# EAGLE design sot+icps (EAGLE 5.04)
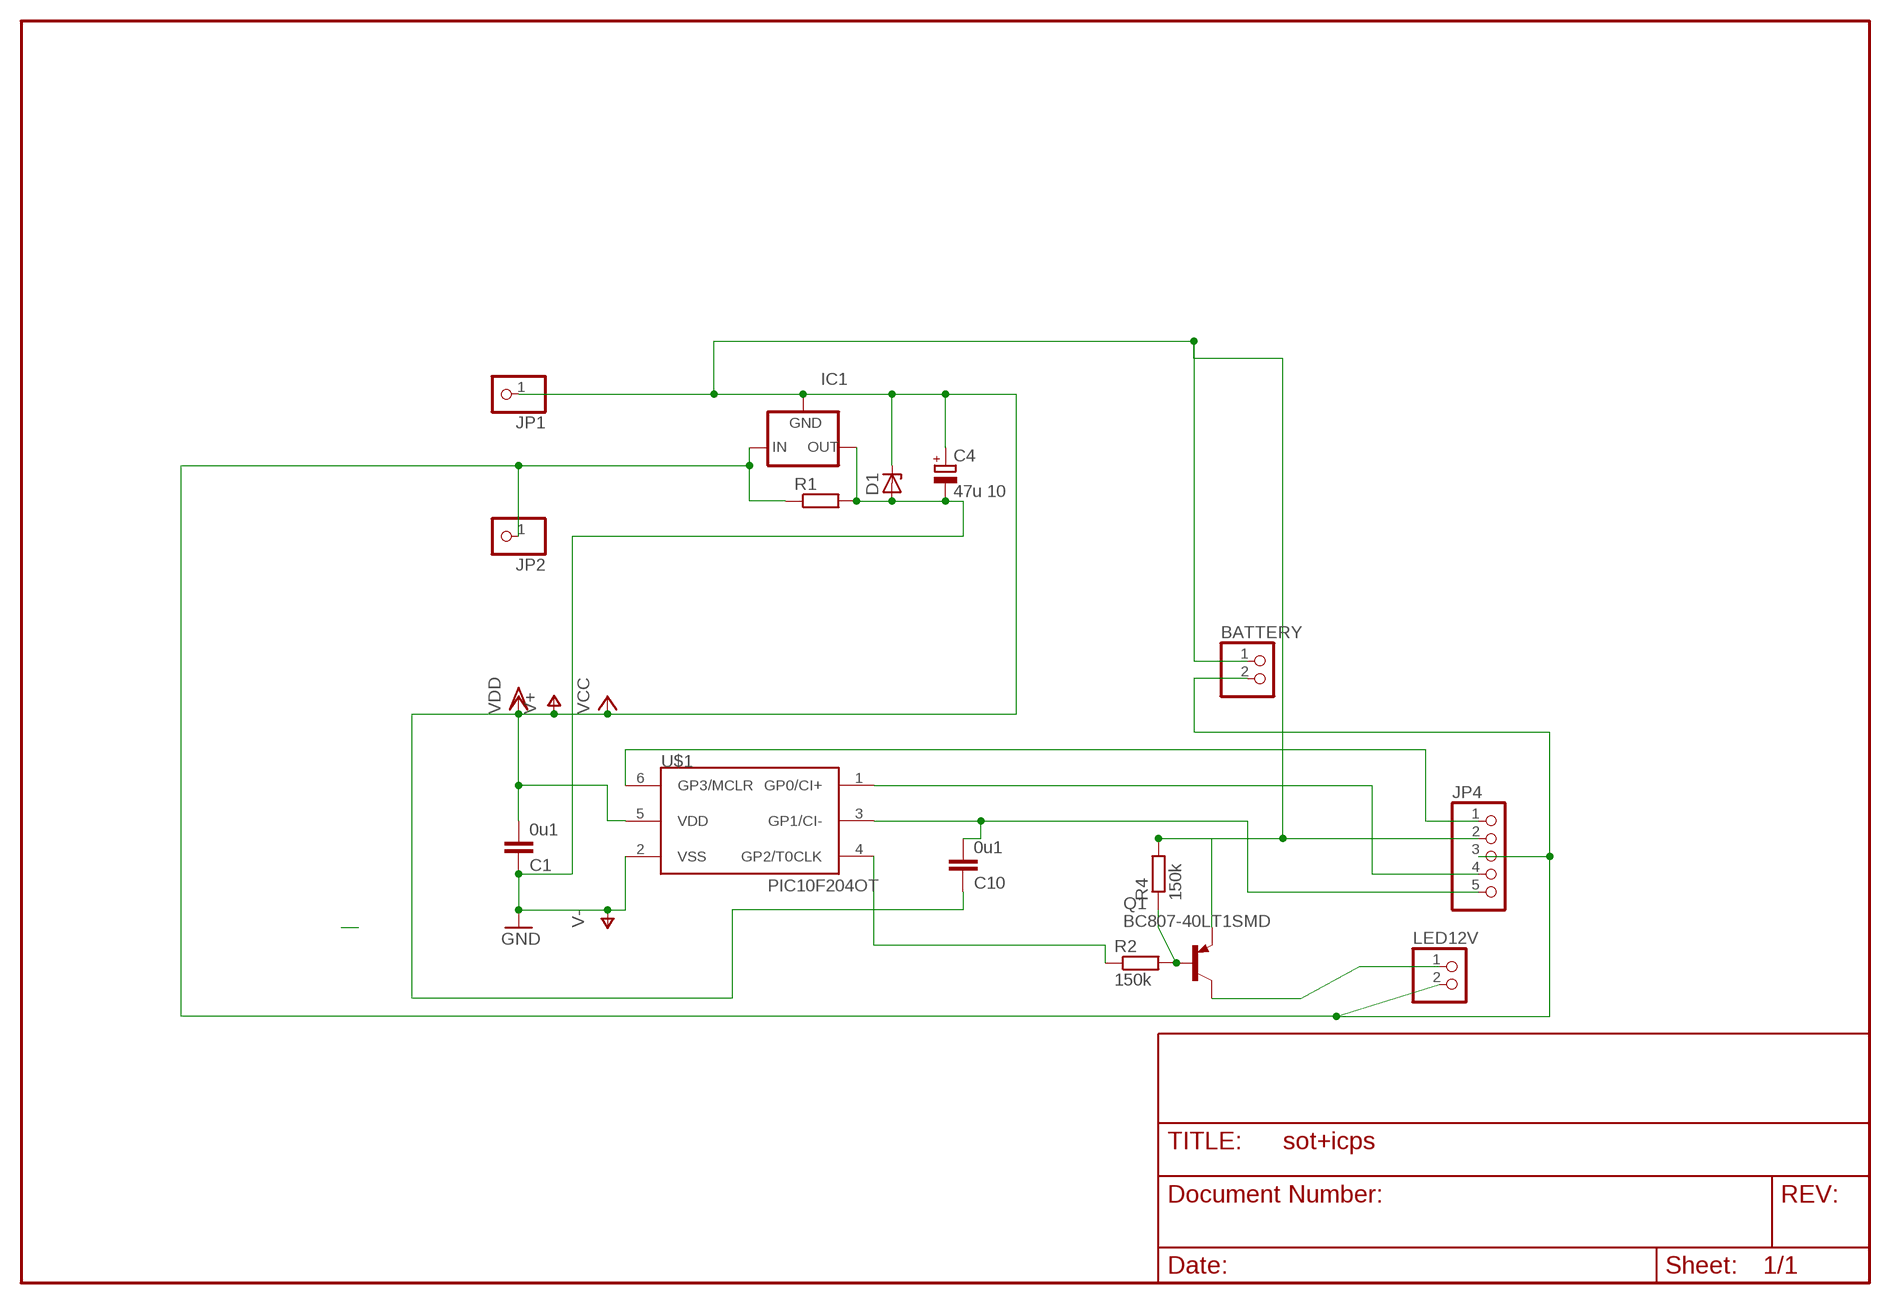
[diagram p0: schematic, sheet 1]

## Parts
BATTERY  PINHD-1X2  [1X02]
C1  0u1  C-EUC1206  [C1206]
C4  47u 10  CPOL-EUE2.5-6  [E2,5-6]
C10  0u1  C-EUC1206  [C1206]
D1  ZENER-DIODESOT23  [SOT23]
IC1  79LXX  [79LXX]
JP1  PINHD-1X1  [1X01]
JP2  PINHD-1X1  [1X01]
JP4  PINHD-1X5  [1X05]
LED12V  PINHD-1X2  [1X02]
Q1  BC807-40LT1SMD  [SOT23-BEC]
R1  R-EU_R0805  [R0805]
R2  150k  R-EU_R0805  [R0805]
R4  150k  R-EU_R0805  [R0805]
U$1  PIC10F204OT  [SOT23-6]

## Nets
GND: C1.1 C4.- D1.1(A) IC1.OUT R1.2 U$1.2(VSS) ; supply symbol labelled V-
N$1: C10.2 JP4.5 U$1.3(GP1/CI-)
N$2: R2.1 U$1.4(GP2/T0CLK)
N$3: JP4.1 U$1.6(GP3/MCLR)
N$4: Q1.B R2.2 R4.1
N$7: BATTERY.2 IC1.IN JP2.1 JP4.3 LED12V.2 R1.1
N$9: LED12V.1 Q1.C
N$12: JP4.4 U$1.1(GP0/CI+)
V+: BATTERY.1 C1.2 C4.+ C10.1 D1.3(C) IC1.GND JP1.1 JP4.2 Q1.E R4.2 U$1.5(VDD) ; supply symbol labelled VDD, VCC

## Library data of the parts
BATTERY LED12V = pinhead:PINHD-1X2: PIN HEADER
C1 C10 = rcl:C-EU: CAPACITOR, European symbol
C4 = rcl:CPOL-EU: POLARIZED CAPACITOR, European symbol
D1 = diode-1:ZENER-DIODE: Z-Diode
IC1 = v-reg:79LXX: VOLTAGE REGULATOR
JP1 JP2 = pinhead:PINHD-1X1: PIN HEADER
JP4 = pinhead:PINHD-1X5: PIN HEADER
Q1 = transistor-pnp:BC807*: PNP Transistror
R1 = rcl-2:R-EU_: RESISTOR, European symbol
R2 R4 = rcl:R-EU_: RESISTOR, European symbol
U$1 = microchip-5:PIC10F2*: uPC nW 0,25/0,5k Program Flash memory Comparator

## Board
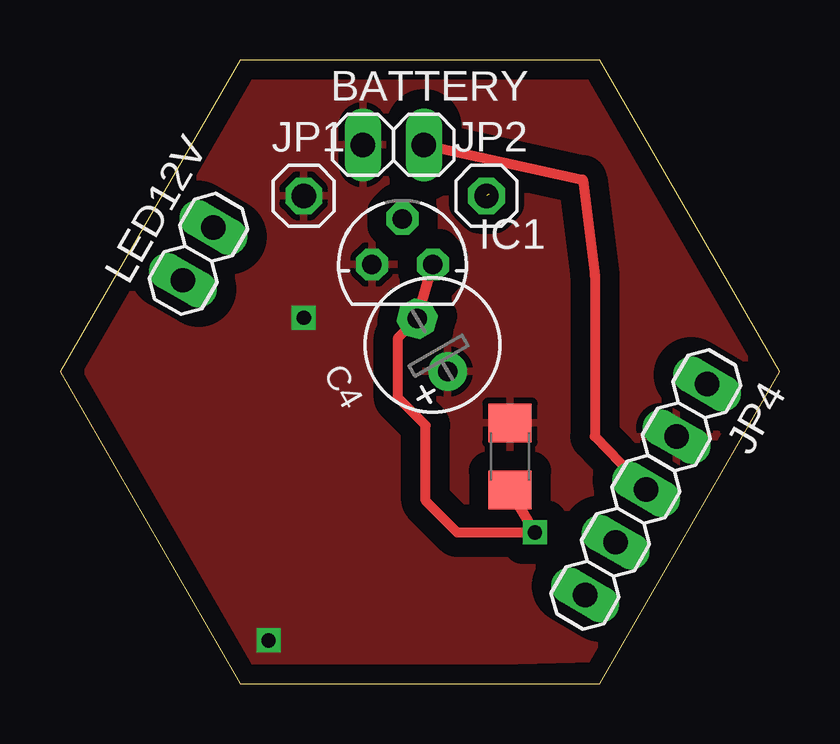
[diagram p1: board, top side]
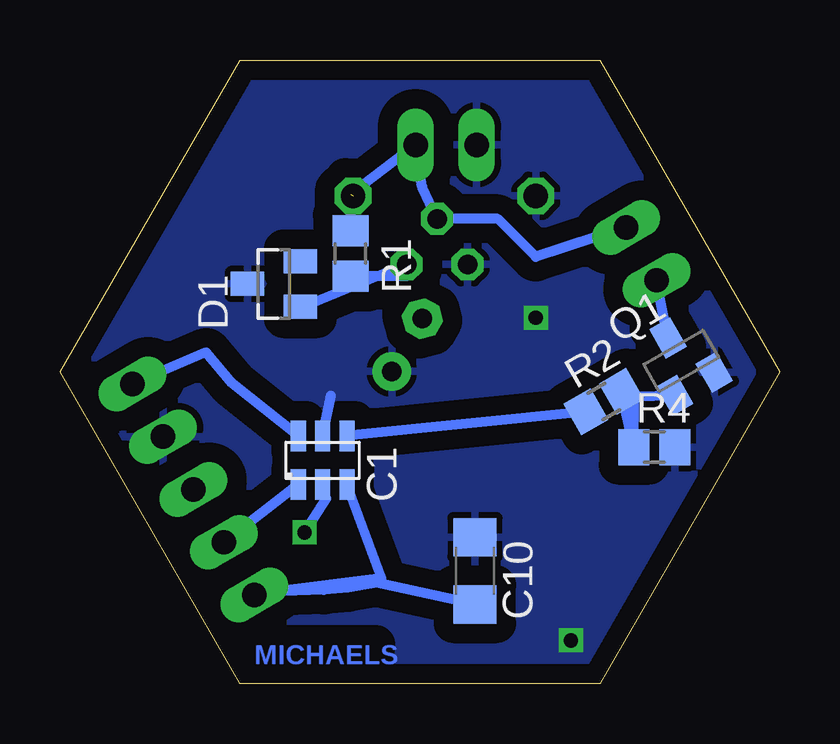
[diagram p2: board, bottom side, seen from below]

Size 30 x 25.98 mm. Coordinates in mm from the lower left corner, seen from the top.
Outline: 7.5,0 22.5,0 30,12.99 22.5,25.98 7.5,25.98 0,12.99 7.5,0
Copper layers (1*16): Top 0.035mm / dielectric 1.5mm / Bottom 0.035mm
Design rules "default *": minimum track width 10mil, minimum drill 24mil, track to track 8mil, track to pad 8mil, pad to pad 8mil, via to via 8mil, smd to smd 8mil, copper to edge 10mil, drill to drill 8mil, minimum pad ring 10mil, minimum via ring 8mil, stop-mask expansion 4mil, vias tented up to drill 0mil, thermal gap 10mil

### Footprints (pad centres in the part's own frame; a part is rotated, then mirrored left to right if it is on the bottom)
1X02 = drill 1.016 long: 1 -1.27,0; 2 1.27,0
C1206 = smd 1.6 x 1.8: 1 -1.4,0; 2 1.4,0
E2,5-6 = drill 0.813 pad 1.6 round: + -1.27,0 | drill 0.813 pad 1.6 octagon: - 1.27,0
SOT23 = smd 1 x 1.4: 1 -0.95,-1.1; 2 0.95,-1.1; 3 0,1.1
79LXX = drill 0.813 octagon: GND -1.27,0; IN 0,1.905; OUT 1.27,0
1X01 = drill 1.016 octagon: 1 0,0
1X05 = drill 1.016 long: 1 -5.08,0; 2 -2.54,0; 3 0,0; 4 2.54,0; 5 5.08,0
SOT23-BEC = smd 1 x 1.4: B -0.95,-1.1; C 0,1.1; E 0.95,-1.1
R0805 = smd 1.3 x 1.5: 1 -0.95,0; 2 0.95,0
R0805' = smd 1.3 x 1.5: 1 -0.85,0; 2 0.85,0
SOT23-6 = smd 0.635 x 1.27: 1 -1.016,-1.016; 2 0,-1.016; 3 1.016,-1.016; 4 1.016,1.016; 5 0,1.016; 6 -1.016,1.016

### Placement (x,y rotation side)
BATTERY  13.9,22.44 0 top
C1  18.76,9.46 90 top
C4  15.53,14.1 120 top
C10  12.7,4.7 270 bottom
D1  21.08,16.65 90 bottom
IC1  14.28,17.46 0 top
JP1  10.16,20.32 0 top
JP2  17.78,20.32 0 top
JP4  24.43,8.08 240 top
LED12V  5.77,17.9 60 top
Q1  4.1,13.44 30 bottom
R1  17.89,17.92 270 bottom
R2  150k  [R0805']  7.33,11.75 30 bottom
R4  150k  [R0805']  5.22,9.85 0 bottom
U$1  19.05,9.3 0 bottom

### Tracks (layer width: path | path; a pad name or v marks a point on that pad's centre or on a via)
GND  (via drill 0.6)
  Top 0.406: C1.1 v19.8,6.3 16.56,6.3 15.24,7.62 15.24,10.76 14.1,11.9 14.1,14.41 C4.- IC1.OUT
  Bottom 0.406: v19.8,6.3 18.9,7.7 U$1.2 | D1.1 19.73,15.74 IC1.OUT 15.55,16.97 R1.2
N$1
  Bottom 0.406: U$1.3 16.6,4.4 21.25,3.82 | 21.25,3.82 JP4.5 | C10.2 16.8,4.2 18,4 19,3.9 21.25,3.82
N$2
  Bottom 0.406: R2.1 U$1.4
N$3
  Bottom 0.406: U$1.6 22.8,12.5 23.9,13.8 JP4.1
N$4
  Bottom 0.406: R2.2 R4.1 6.06,11.96 Q1.B
N$7  (1 unrouted)
  Top 0.406: JP4.3 22.3,10.3 22.3,17 21.8,21 BATTERY.2
  Bottom 0.406: LED12V.2 10.16,17.78 11.74,19.36 IC1.IN 14.9,20.7 BATTERY.2 17.89,20.39 R1.1
N$9
  Bottom 0.406: Q1.C LED12V.1
N$12
  Bottom 0.406: U$1.1 JP4.4
V+  (via drill 0.6)
  Bottom 0.406: U$1.5 18.7,12
  other vias: 8.7,1.8 10.16,15.24
  pour Bottom (isolate 0.813, rank 4): 22.49,0.55 6.94,0.85 0.37,12.61 7.94,25.55 22.3,25.48 24.35,22.44 30.04,12.81
  pour Top (isolate 0.813, rank 4): 22.51,26.2 30.98,12.29 23.05,1.05 7.24,0.65 -0.28,14.57 6.57,25.9

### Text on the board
Bottom: MICHAELS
